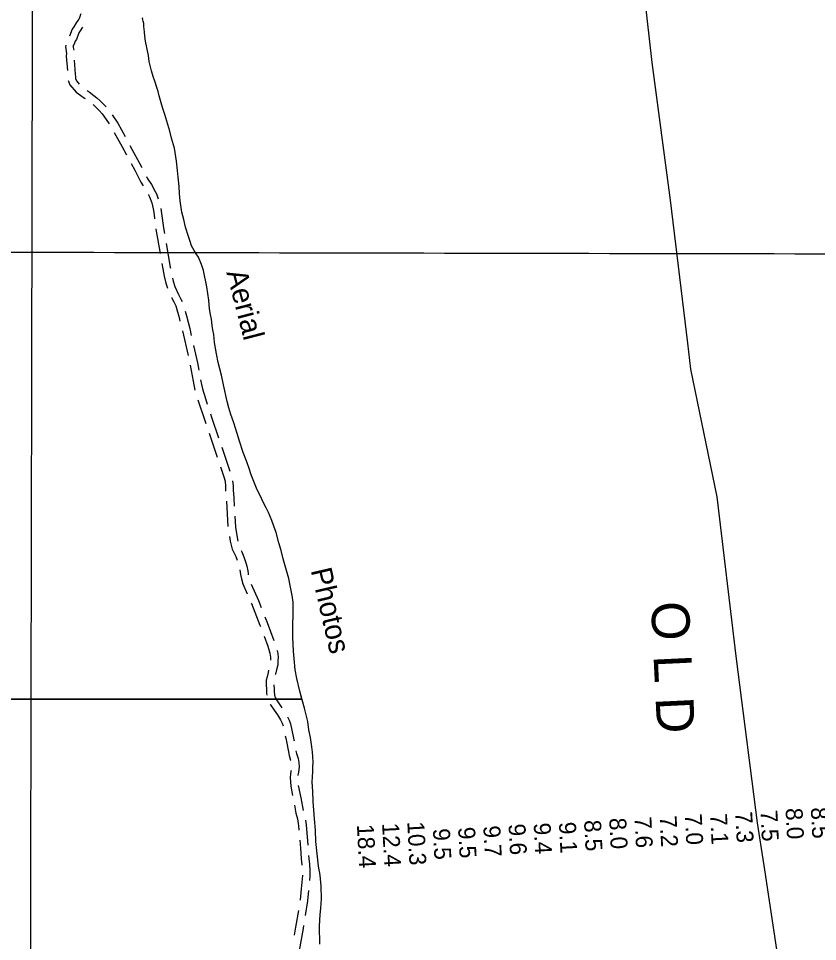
# Model space of a CAD drawing. Extents: x 3192952 to 3230831, y 849296 to 874698.
# Drawn here: x 3207564 to 3210731, y 858041 to 861699 of the extents above; entities that cross this region are included whole.
import ezdxf

# ---------------------------------------------------------------- set-up
doc = ezdxf.new("R2010")
doc.units = 0
for name, color, linetype in [('V-GRID-MAJR', 7, 'Continuous'), ('V-RIVR-IDEN', 7, 'Continuous'), ('V-RIVR-RANG', 7, 'Continuous'), ('V-ROAD-CNTR', 7, 'Continuous'), ('V-SITE-VEGE', 7, 'Continuous'), ('V-TOPO-BNDY', 7, 'Continuous'), ('V-TOPO-SHOR', 7, 'Continuous')]:
    doc.layers.add(name, color=color, linetype=linetype)

msp = doc.modelspace()

# ---------------------------------------------------------------- linework, layer by layer
at = {"layer": 'V-GRID-MAJR'}
for points in [[(3207605.446, 854713.525), (3207617.785, 860772.968), (3207630.13, 866835.496), (3207642.475, 872898.066), (3207642.481, 872901.108)], [(3197158.4390000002, 860795.787), (3202388.111, 860783.997), (3207617.785, 860772.968), (3212847.46, 860762.699), (3218077.137, 860753.191), (3223306.816, 860744.443), (3228536.495, 860736.457), (3228536.4960000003, 860736.457)]]:
    msp.add_spline(points, degree=3, dxfattribs=at)
at = {"layer": 'V-ROAD-CNTR'}
for p, q in [((3208213.826266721, 860461.4124769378), (3208235.912454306, 860363.8820339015)), ((3208319.3131240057, 860055.5952207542), (3208351.3451423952, 859960.8702590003)), ((3208369.8423514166, 859999.8213750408), (3208401.8743793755, 859905.0963849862))]:
    msp.add_line(p, q, dxfattribs=at)
for points in [[(3207810.4910056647, 861717.7183139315), (3207810.166320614, 861714.6589927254), (3207805.9629627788, 861701.3251246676), (3207802.9279060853, 861696.2592289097), (3207798.7438753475, 861691.4055059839), (3207793.0401801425, 861681.3239112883), (3207783.744000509, 861666.4862923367), (3207776.6917882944, 861656.738081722), (3207766.3573222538, 861629.6777769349), (3207766.0711100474, 861629.2217272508)], [(3207817.8928515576, 861664.4865559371), (3207808.635999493, 861649.7117076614), (3207803.3102117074, 861642.3499182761), (3207793.3326777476, 861616.2242230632), (3207788.6515859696, 861608.7653852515), (3207784.023901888, 861597.3117227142), (3207781.117668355, 861591.9579846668), (3207780.799636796, 861586.8994313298), (3207781.0024326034, 861583.5634402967), (3207782.9053705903, 861573.8982014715)], [(3207751.108880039, 861592.760320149), (3207750.7423632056, 861586.9305686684), (3207751.179567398, 861579.7385597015), (3207753.464551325, 861568.1328660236), (3207754.24587235, 861561.1190012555), (3207753.488454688, 861549.4553564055), (3207757.827223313, 861493.2453327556)], [(3207784.765945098, 861534.0612007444), (3207789.032446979, 861478.7874140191), (3207789.3764270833, 861468.0794587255), (3207790.248401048, 861461.0111736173), (3207793.7544302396, 861451.5380527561), (3207804.7092748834, 861439.035952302)], [(3207761.069248, 861453.4198467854), (3207767.541569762, 861435.931947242), (3207793.0741762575, 861406.7931304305), (3207811.558488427, 861394.3053975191), (3207826.1483414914, 861383.7408364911), (3207827.96742014, 861382.3509295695)], [(3207835.5430226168, 861413.9771914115), (3207844.0556585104, 861407.813163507), (3207862.185121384, 861393.960949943), (3207874.131601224, 861384.6147327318), (3207887.377152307, 861372.8806384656), (3207904.80635216, 861355.4194792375), (3207911.0167117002, 861348.7143631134)], [(3207859.378782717, 861357.6051754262), (3207866.7948476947, 861351.0353615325), (3207883.1776478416, 861334.6225207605), (3207895.4800179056, 861321.3400659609), (3207901.8996758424, 861312.6193779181), (3207922.9373808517, 861281.0113290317)], [(3207935.0993709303, 861316.8829561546), (3207957.241771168, 861283.6151605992), (3207986.4288158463, 861231.1525162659)], [(3207943.4460857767, 861246.7051299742), (3207974.641337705, 861190.6328066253), (3207991.71997077, 861159.1327808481)], [(3208005.7781263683, 861196.1455417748), (3208051.548795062, 861111.7255979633), (3208053.3290326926, 861108.1783880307)], [(3208010.7852074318, 861123.968640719), (3208024.949204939, 861097.8444020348), (3208048.550500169, 861050.8176751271), (3208058.6714469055, 861036.3613421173)], [(3208071.264056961, 861072.4419811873), (3208074.3814998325, 861066.230324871), (3208091.697612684, 861041.4967203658), (3208106.067436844, 861013.9675988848), (3208111.0300001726, 861004.0887278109), (3208118.0536102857, 860984.582159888)], [(3208078.591381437, 861001.7736310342), (3208079.364563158, 861000.2924011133), (3208083.413999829, 860992.2312721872), (3208091.8089061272, 860968.9162237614), (3208095.7293886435, 860956.5841595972), (3208097.8976867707, 860944.5548107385), (3208101.381360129, 860922.1315501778), (3208103.461084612, 860905.590613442)], [(3208128.039123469, 860945.9609314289), (3208131.092639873, 860926.3064498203), (3208138.269666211, 860869.2244951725), (3208142.1160402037, 860846.9765264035)], [(3208108.4510756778, 860865.9030840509), (3208108.590333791, 860864.7955048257), (3208125.435834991, 860767.3587539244)], [(3208148.9303067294, 860807.5618493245), (3208165.266307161, 860713.0721226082), (3208166.109371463, 860709.0525175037)], [(3208132.250103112, 860727.9440676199), (3208135.7956928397, 860707.43587739), (3208141.8498655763, 860678.5704829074), (3208148.5189270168, 860649.8889987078), (3208154.7134998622, 860630.6127085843)], [(3208174.648383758, 860669.9768699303), (3208177.4590729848, 860657.8890012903), (3208184.237335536, 860636.7963838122), (3208198.2098646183, 860605.8293442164), (3208205.959725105, 860589.2279226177), (3208212.155691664, 860577.6403510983)], [(3208170.654725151, 860593.9560699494), (3208170.9441353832, 860593.3146557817), (3208179.120274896, 860575.8000773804), (3208187.533714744, 860560.065432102), (3208192.128128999, 860546.0002088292), (3208200.236199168, 860513.7750938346), (3208203.7943121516, 860500.1330087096)], [(3208224.628762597, 860539.7777625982), (3208229.297800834, 860521.2209061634), (3208242.535841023, 860470.4652185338), (3208248.810774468, 860442.7557265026)], [(3208257.645249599, 860403.7435488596), (3208273.4048278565, 860334.150793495), (3208278.4223535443, 860305.9485617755)], [(3208244.5905502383, 860324.8382551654), (3208255.8478848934, 860261.5636492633), (3208263.4376528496, 860226.6590466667)], [(3208285.4595908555, 860266.5733548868), (3208293.1120922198, 860231.3802474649), (3208304.736866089, 860193.1602018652), (3208312.355726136, 860170.3804247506)], [(3208274.848595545, 860188.3314477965), (3208276.1551339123, 860184.0357981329), (3208301.0284636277, 860109.6665481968), (3208306.5003166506, 860093.4852054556)], [(3208325.0417167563, 860132.4503358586), (3208329.463536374, 860119.2294518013), (3208357.029540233, 860037.7113710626)], [(3208364.1579497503, 859922.9802742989), (3208377.578990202, 859883.2916250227), (3208382.7419333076, 859865.3729611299), (3208384.3722498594, 859845.783745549), (3208384.6227073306, 859828.9179394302), (3208384.8776013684, 859826.0001272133)], [(3208412.735401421, 859866.697669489), (3208414.3537501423, 859847.2522544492), (3208414.6032926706, 859830.4480605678), (3208417.1943600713, 859800.7877037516), (3208419.250378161, 859766.9456244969)], [(3208388.0296206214, 859786.128846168), (3208391.0832749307, 859735.8656643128), (3208393.621510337, 859686.2917666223)], [(3208421.5756497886, 859727.0166772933), (3208423.814214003, 859683.2956130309), (3208432.3706331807, 859633.859495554), (3208433.8675501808, 859627.9971998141)], [(3208399.686034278, 859646.7931595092), (3208403.0113668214, 859627.5805044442), (3208411.078163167, 859595.9889426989), (3208416.1719695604, 859585.6487192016), (3208422.074619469, 859572.6622872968), (3208424.8458515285, 859567.1299371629), (3208430.369970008, 859552.2027632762)], [(3208446.9666057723, 859590.3984400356), (3208449.151380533, 859585.5917127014), (3208452.408148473, 859579.0900628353), (3208458.6088668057, 859562.3345929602), (3208462.747547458, 859550.4803769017), (3208466.670168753, 859537.7251160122), (3208469.307587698, 859528.2734497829), (3208472.7337949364, 859509.6174113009), (3208473.9128072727, 859500.0755667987), (3208474.8223924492, 859494.8680180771)], [(3208441.458209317, 859513.8311753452), (3208443.068205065, 859505.0645886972), (3208444.2311927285, 859495.6524331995), (3208447.3240654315, 859477.9451467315), (3208453.155280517, 859458.1310611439), (3208470.3520918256, 859418.7485692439)], [(3208486.482476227, 859456.7757659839), (3208514.676913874, 859392.2075624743), (3208525.579288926, 859364.748229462)], [(3208486.359036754, 859382.0909954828), (3208486.9810861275, 859380.6664375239), (3208521.0385729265, 859294.8873419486), (3208523.211428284, 859289.1310641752)], [(3208540.3399105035, 859327.5713004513), (3208549.015427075, 859305.7206580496), (3208576.028159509, 859234.1591568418)], [(3208537.337559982, 859251.708445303), (3208552.363176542, 859211.9029320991), (3208560.4998666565, 859183.772744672), (3208562.856694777, 859167.645144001), (3208562.5272593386, 859155.7839975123)], [(3208588.169768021, 859196.0799926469), (3208589.888133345, 859190.139255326), (3208592.9173052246, 859169.4108559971), (3208592.4236639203, 859151.6375652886), (3208591.3484299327, 859137.0629202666), (3208586.7101800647, 859118.2422674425), (3208582.0750864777, 859100.3412163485), (3208581.499707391, 859097.8109476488)], [(3208555.2953049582, 859116.5988471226), (3208552.9209135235, 859107.4287836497), (3208549.0504586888, 859090.408195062), (3208546.245886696, 859076.6280064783), (3208545.5476452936, 859059.6231774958), (3208546.6880799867, 859039.3989886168), (3208547.172604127, 859025.832312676), (3208548.6437285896, 859017.8075316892)], [(3208575.66416573, 859058.4020059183), (3208576.6579200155, 859040.7790113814), (3208577.075395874, 859029.0896873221), (3208580.4547666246, 859010.6556860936), (3208580.6725353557, 859009.9436329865), (3208588.5765059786, 858994.518085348), (3208602.1506390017, 858975.5062032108), (3208607.979772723, 858966.8048938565)], [(3208562.0452771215, 858980.5098923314), (3208562.881494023, 858978.8779146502), (3208577.4753609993, 858958.4377967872), (3208590.0311802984, 858939.6953775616), (3208602.5407313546, 858919.195504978)], [(3208602.1585971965, 858919.8592600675), (3208609.1851699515, 858906.900016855), (3208612.7847332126, 858896.3278145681), (3208612.8998416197, 858895.7734752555)], [(3208629.5710516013, 858932.2412956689), (3208636.7668300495, 858918.9699831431), (3208641.781266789, 858904.24218543), (3208652.2884599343, 858853.6416222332), (3208655.5951069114, 858840.8048876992), (3208656.372503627, 858836.4893619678)], [(3208621.0282981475, 858856.6284369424), (3208623.0595400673, 858846.846377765), (3208626.26689309, 858834.395112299), (3208633.7203054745, 858793.0193355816), (3208637.332928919, 858778.5646214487), (3208642.6877530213, 858760.0765918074), (3208642.857137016, 858759.1340850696)], [(3208663.6096327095, 858797.1542785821), (3208666.303071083, 858786.3773785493), (3208671.93824698, 858766.9214081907), (3208674.9327049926, 858750.2592857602), (3208676.227052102, 858731.7882315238), (3208673.6036971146, 858712.1723415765), (3208671.679204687, 858700.5474840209), (3208671.565212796, 858698.9345284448)], [(3208644.3149168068, 858719.4875727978), (3208643.930302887, 858716.6116584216), (3208641.8527953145, 858704.0625159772), (3208640.9701064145, 858691.5726979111), (3208642.8039803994, 858656.7598690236), (3208650.058015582, 858620.4875259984)], [(3208672.944845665, 858659.0259119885), (3208682.496422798, 858611.2651728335), (3208691.878766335, 858560.8521750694)], [(3208657.575469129, 858581.2066744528), (3208663.5080967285, 858549.3296129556), (3208669.6346165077, 858527.9095946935), (3208674.1448423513, 858499.6289247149), (3208675.6718063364, 858483.0495303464)], [(3208700.961981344, 858521.9637523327), (3208703.9271576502, 858503.3710752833), (3208711.369446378, 858422.5645591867)], [(3208679.3391716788, 858443.2301915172), (3208682.3041854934, 858411.0368105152), (3208683.55447775, 858391.1289880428), (3208684.3050776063, 858368.3265972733), (3208686.8242215, 858345.4542258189), (3208686.9463266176, 858343.5700897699)], [(3208713.8497494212, 858382.6525925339), (3208714.2509223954, 858370.4654027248), (3208716.7177785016, 858348.0677741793), (3208718.3552840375, 858322.8003384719), (3208719.1615592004, 858301.9041965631), (3208717.2228703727, 858282.9621396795)], [(3208689.072644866, 858303.6300213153), (3208689.102440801, 858302.8578034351), (3208686.393163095, 858276.3866690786), (3208684.3000296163, 858249.3939477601), (3208679.8901619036, 858206.2089826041), (3208679.5468468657, 858204.1022899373)], [(3208713.8143758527, 858243.1102714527), (3208709.643838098, 858202.269017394), (3208700.162822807, 858144.0904257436)], [(3208673.113191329, 858164.6232882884), (3208662.312791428, 858098.3485238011), (3208656.4522183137, 858066.0248984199)], [(3208693.729166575, 858104.6114198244), (3208691.8792085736, 858093.2594761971), (3208676.0910593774, 858006.1809243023)]]:
    msp.add_lwpolyline(points, dxfattribs=at)
at = {"layer": 'V-SITE-VEGE'}
for p, q in [((3208055.7970000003, 861699.0279999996), (3208057.1420000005, 861702.9869999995)), ((3208058.375, 861688.4419999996), (3208055.7970000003, 861699.0279999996)), ((3208060.9620000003, 861679.1769999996), (3208058.375, 861688.4419999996)), ((3208060.89, 861667.2839999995), (3208060.9620000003, 861679.1769999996)), ((3208063.4050000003, 861646.1259999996), (3208060.89, 861667.2839999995)), ((3208064.619, 861628.9419999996), (3208063.4050000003, 861646.1259999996)), ((3208067.143, 861609.1049999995), (3208064.619, 861628.9419999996)), ((3208078.6890000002, 861552.2129999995), (3208067.143, 861609.1049999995)), ((3208082.509, 861528.4029999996), (3208078.6890000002, 861552.2129999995)), ((3208091.532, 861491.3489999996), (3208082.509, 861528.4029999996)), ((3208098.004, 861468.8429999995), (3208091.532, 861491.3489999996)), ((3208104.498, 861450.3049999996), (3208098.004, 861468.8429999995)), ((3208112.272, 861425.1509999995), (3208104.498, 861450.3049999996)), ((3208117.4620000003, 861409.2649999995), (3208112.272, 861425.1509999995)), ((3208121.322, 861392.0599999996), (3208117.4620000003, 861409.2649999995)), ((3208129.08, 861364.2619999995), (3208121.322, 861392.0599999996)), ((3208135.552, 861341.7589999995), (3208129.08, 861364.2619999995)), ((3208143.343, 861319.2469999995), (3208135.552, 861341.7589999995)), ((3208156.315, 861279.5239999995), (3208143.343, 861319.2469999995)), ((3208164.083, 861253.0499999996), (3208156.315, 861279.5239999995)), ((3208170.522, 861225.2599999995), (3208164.083, 861253.0499999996)), ((3208182.173, 861185.5459999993), (3208170.522, 861225.2599999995)), ((3208189.787, 861133.9649999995), (3208182.173, 861185.5459999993)), ((3208193.5270000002, 861096.9409999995), (3208189.787, 861133.9649999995)), ((3208197.33, 861070.4889999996), (3208193.5270000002, 861096.9409999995)), ((3208201.0670000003, 861033.4669999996), (3208197.33, 861070.4889999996)), ((3208202.221, 861005.7109999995), (3208201.0670000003, 861033.4669999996)), ((3208204.686, 860976.6229999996), (3208202.221, 861005.7109999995)), ((3208211.021, 860931.6549999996), (3208204.686, 860976.6229999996)), ((3208218.77, 860902.5359999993), (3208211.021, 860931.6549999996)), ((3208226.514, 860872.0969999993), (3208218.77, 860902.5359999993)), ((3208238.181, 860835.0259999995), (3208226.514, 860872.0969999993)), ((3208244.669, 860815.1649999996), (3208238.181, 860835.0259999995)), ((3208249.849, 860797.9549999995), (3208244.669, 860815.1649999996)), ((3208260.308, 860779.3899999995), (3208249.849, 860797.9549999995)), ((3208268.156, 860766.1289999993), (3208260.308, 860779.3899999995)), ((3208277.325, 860752.8579999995), (3208268.156, 860766.1289999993)), ((3208289.039, 860723.7149999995), (3208277.325, 860752.8579999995)), ((3208296.826, 860699.8829999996), (3208289.039, 860723.7149999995)), ((3208310.965, 860635.0469999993), (3208296.826, 860699.8829999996)), ((3208314.768, 860608.5949999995), (3208310.965, 860635.0469999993)), ((3208318.58, 860583.4639999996), (3208314.768, 860608.5949999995)), ((3208321.0130000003, 860549.0929999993), (3208318.58, 860583.4639999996)), ((3208324.84, 860526.6059999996), (3208321.0130000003, 860549.0929999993)), ((3208328.693, 860508.0809999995), (3208324.84, 860526.6059999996)), ((3208331.181, 860482.9589999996), (3208328.693, 860508.0809999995)), ((3208333.721, 860465.7659999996), (3208331.181, 860482.9589999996)), ((3208337.573, 860447.2419999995), (3208333.721, 860465.7659999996)), ((3208341.343, 860415.5039999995), (3208337.573, 860447.2419999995)), ((3208348.999, 860370.5299999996), (3208341.343, 860415.5039999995)), ((3208355.397, 860336.1329999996), (3208348.999, 860370.5299999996)), ((3208368.305, 860285.8409999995), (3208355.397, 860336.1329999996)), ((3208375.999, 860247.4709999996), (3208368.305, 860285.8409999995)), ((3208391.454, 860181.3069999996), (3208375.999, 860247.4709999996)), ((3208397.907, 860156.1589999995), (3208391.454, 860181.3069999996)), ((3208405.6750000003, 860129.6849999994), (3208397.907, 860156.1589999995)), ((3208417.367, 860096.5769999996), (3208405.6750000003, 860129.6849999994)), ((3208430.323, 860054.2119999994), (3208417.367, 860096.5769999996)), ((3208439.387, 860023.7639999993), (3208430.323, 860054.2119999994)), ((3208454.97, 859978.7389999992), (3208439.387, 860023.7639999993)), ((3208469.282, 859941.6539999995), (3208454.97, 859978.7389999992)), ((3208478.369, 859915.1689999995), (3208469.282, 859941.6539999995)), ((3208486.145, 859890.0159999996), (3208478.369, 859915.1689999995)), ((3208509.576, 859831.7289999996), (3208486.145, 859890.0159999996)), ((3208521.332, 859809.1929999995), (3208509.5760000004, 859831.7289999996)), ((3208535.69, 859780.0359999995), (3208521.332, 859809.1929999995)), ((3208546.139, 859760.1499999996), (3208535.69, 859780.0359999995)), ((3208555.2770000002, 859741.5949999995), (3208546.139, 859760.1499999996)), ((3208568.298, 859709.7999999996), (3208555.2770000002, 859741.5949999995)), ((3208576.089, 859687.2879999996), (3208568.298, 859709.7999999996)), ((3208585.186, 859662.1259999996), (3208576.089, 859687.2879999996)), ((3208595.508, 859621.0989999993), (3208585.186, 859662.1259999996)), ((3208604.571, 859590.6509999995), (3208595.508, 859621.0989999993)), ((3208613.623, 859557.5599999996), (3208604.571, 859590.6509999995)), ((3208626.554, 859511.2319999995), (3208613.623, 859557.5599999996)), ((3208635.61, 859479.4609999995), (3208626.554, 859511.2319999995)), ((3208640.728, 859451.6799999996), (3208635.61, 859479.4609999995)), ((3208648.414, 859411.9919999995), (3208640.728, 859451.6799999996)), ((3208652.217, 859385.5399999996), (3208648.414, 859411.9919999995)), ((3208651.374, 859246.7959999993), (3208652.217, 859385.5399999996)), ((3208653.678, 859191.2809999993), (3208651.374, 859246.7959999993)), ((3208656.143, 859162.1949999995), (3208653.678, 859191.2809999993)), ((3208661.157, 859117.2329999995), (3208656.143, 859162.1949999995)), ((3208667.563, 859084.1579999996), (3208661.157, 859117.2329999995)), ((3208679.149, 859033.8739999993), (3208667.563, 859084.1579999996)), ((3208687.468, 859002.2099999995), (3208679.149, 859033.8739999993)), ((3207018.754, 859002.2099999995), (3208687.468, 859002.2099999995)), ((3208687.468, 859002.2099999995), (3207018.754, 859002.2099999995)), ((3208688.1900000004, 858999.4609999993), (3208687.468, 859002.2099999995)), ((3208697.2380000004, 858966.3719999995), (3208688.1900000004, 858999.4609999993)), ((3208710.131, 858913.4349999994), (3208697.238, 858966.3719999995)), ((3208715.216, 858880.3699999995), (3208710.131, 858913.4349999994)), ((3208721.636, 858849.9369999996), (3208715.216, 858880.3699999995)), ((3208726.697, 858812.9069999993), (3208721.636, 858849.9369999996)), ((3208729.2120000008, 858791.7489999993), (3208726.697, 858812.9069999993)), ((3208730.428, 858774.5619999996), (3208729.2120000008, 858791.7489999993)), ((3208731.606, 858750.7679999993), (3208730.428, 858774.5619999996)), ((3208730.066, 858715.0979999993), (3208730.179, 858733.5979999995)), ((3208730.1790000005, 858733.5979999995), (3208731.6060000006, 858750.7679999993)), ((3208728.487, 858672.8239999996), (3208730.066, 858715.0979999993)), ((3208730.914, 858637.1289999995), (3208728.487, 858672.8239999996)), ((3208731.985, 858596.1589999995), (3208730.914, 858637.1289999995)), ((3208736.853, 858527.4159999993), (3208731.985, 858596.1589999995)), ((3208740.543, 858482.4619999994), (3208736.853, 858527.4159999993)), ((3208742.913, 858437.5209999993), (3208740.543, 858482.4619999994)), ((3208752.889, 858339.6729999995), (3208742.913, 858437.5209999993)), ((3208759.279, 858303.9559999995), (3208752.889, 858339.6729999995)), ((3208762.977, 858260.3279999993), (3208759.279, 858303.9559999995)), ((3208765.3140000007, 858210.0979999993), (3208762.9770000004, 858260.3279999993)), ((3208762.447, 858173.1159999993), (3208765.3140000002, 858210.0979999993)), ((3208756.727, 858101.7919999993), (3208759.6510000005, 858148.0279999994)), ((3208759.6510000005, 858148.0279999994), (3208762.447, 858173.1159999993)), ((3208758.9340000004, 858030.4209999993), (3208756.7270000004, 858101.7919999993))]:
    msp.add_line(p, q, dxfattribs=at)
at = {"layer": 'V-TOPO-BNDY'}
for p, q in [((3209999.691000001, 862195.7669999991), (3210074.052000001, 861524.8069999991)), ((3210074.052000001, 861524.8069999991), (3210146.991000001, 860978.912999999)), ((3210146.991000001, 860978.912999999), (3210215.353000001, 860412.0809999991)), ((3210215.353000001, 860412.0809999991), (3210227.617000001, 860309.8289999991)), ((3210227.617000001, 860309.8289999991), (3210331.338000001, 859803.5179999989)), ((3210331.338000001, 859803.5179999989), (3210407.282000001, 859172.5769999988)), ((3210407.282000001, 859172.5769999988), (3210414.880000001, 859109.7769999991)), ((3210414.880000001, 859109.7769999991), (3210491.956000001, 858510.981999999)), ((3210491.956000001, 858510.981999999), (3210520.378000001, 858325.785999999)), ((3210520.378000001, 858325.785999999), (3210581.919000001, 857917.903999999))]:
    msp.add_line(p, q, dxfattribs=at)
at = {"layer": 'V-TOPO-SHOR'}
for points in [[(3208535.690000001, 859780.035999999), (3208521.332000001, 859809.192999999), (3208509.576000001, 859831.7289999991), (3208486.145000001, 859890.015999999), (3208478.369000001, 859915.1689999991), (3208469.282000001, 859941.653999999), (3208454.970000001, 859978.7409999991), (3208439.387000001, 860023.763999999), (3208430.323000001, 860054.211999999), (3208417.367000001, 860096.5769999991), (3208405.675000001, 860129.684999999), (3208397.907000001, 860156.158999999), (3208391.454000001, 860181.3069999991), (3208375.9990000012, 860247.4709999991), (3208368.3030000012, 860285.8409999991), (3208355.397000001, 860336.1329999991), (3208348.9990000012, 860370.5299999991), (3208341.343000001, 860415.503999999), (3208337.573000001, 860447.241999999), (3208333.721000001, 860465.765999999), (3208331.181000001, 860482.9589999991), (3208328.693000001, 860508.0809999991), (3208324.8400000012, 860526.6059999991), (3208321.013000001, 860549.0929999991), (3208318.580000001, 860583.4639999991), (3208314.768000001, 860608.594999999), (3208310.9650000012, 860635.0469999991), (3208296.824000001, 860699.8829999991), (3208289.039000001, 860723.714999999), (3208277.325000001, 860752.8579999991), (3208268.156000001, 860766.128999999), (3208260.308000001, 860779.3899999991), (3208249.849000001, 860797.954999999), (3208244.667000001, 860815.1649999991), (3208238.181000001, 860835.025999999), (3208226.514000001, 860872.096999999), (3208218.770000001, 860902.535999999), (3208211.021000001, 860931.6569999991), (3208204.686000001, 860976.6229999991), (3208202.221000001, 861005.7109999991), (3208201.067000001, 861033.466999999), (3208197.330000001, 861070.488999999), (3208193.527000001, 861096.9409999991), (3208189.787000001, 861133.964999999), (3208182.173000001, 861185.545999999), (3208170.522000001, 861225.2599999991), (3208164.083000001, 861253.0499999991), (3208156.315000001, 861279.523999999), (3208143.343000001, 861319.246999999), (3208135.552000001, 861341.758999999), (3208129.080000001, 861364.261999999), (3208121.322000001, 861392.059999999), (3208117.462000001, 861409.2629999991), (3208112.272000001, 861425.150999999), (3208104.498000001, 861450.3049999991), (3208098.004000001, 861468.844999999), (3208091.532000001, 861491.3489999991), (3208082.509000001, 861528.4029999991), (3208078.689000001, 861552.212999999), (3208067.143000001, 861609.104999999), (3208064.619000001, 861628.9419999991), (3208063.405000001, 861646.1259999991), (3208060.890000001, 861667.283999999), (3208060.962000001, 861679.1769999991), (3208058.375000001, 861688.4439999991), (3208055.797000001, 861699.0299999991), (3208057.142000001, 861702.986999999)], [(3208758.934000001, 858030.420999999), (3208756.727000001, 858101.7919999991), (3208759.651000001, 858148.025999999), (3208762.447000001, 858173.1159999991), (3208765.314000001, 858210.0979999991), (3208762.977000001, 858260.327999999), (3208759.279000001, 858303.9559999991), (3208752.889000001, 858339.672999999), (3208742.913000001, 858437.520999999), (3208740.543000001, 858482.4639999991), (3208736.853000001, 858527.415999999), (3208731.985000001, 858596.158999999), (3208730.914000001, 858637.128999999), (3208728.487000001, 858672.8239999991), (3208730.066000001, 858715.0979999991), (3208730.179000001, 858733.5979999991), (3208731.606000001, 858750.7679999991), (3208730.4280000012, 858774.5619999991), (3208729.212000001, 858791.748999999), (3208726.697000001, 858812.9069999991), (3208721.636000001, 858849.9369999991), (3208715.216000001, 858880.3699999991), (3208710.131000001, 858913.434999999), (3208697.238000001, 858966.371999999), (3208688.190000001, 858999.4609999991), (3208679.149000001, 859033.873999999), (3208667.563000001, 859084.157999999), (3208661.157000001, 859117.2329999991), (3208656.143000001, 859162.192999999), (3208653.6780000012, 859191.280999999), (3208651.3740000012, 859246.7939999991), (3208652.217000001, 859385.5399999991), (3208648.414000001, 859411.991999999), (3208640.728000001, 859451.6799999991), (3208635.610000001, 859479.4609999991), (3208626.554000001, 859511.231999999), (3208613.623000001, 859557.559999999), (3208604.573000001, 859590.650999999), (3208595.508000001, 859621.0989999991), (3208585.186000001, 859662.1259999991), (3208576.089000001, 859687.287999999), (3208568.298000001, 859709.7999999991), (3208555.277000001, 859741.594999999), (3208546.139000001, 859760.1499999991), (3208535.690000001, 859780.035999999)]]:
    msp.add_lwpolyline(points, dxfattribs=at)

# ---------------------------------------------------------------- texts
at = {"layer": 'V-RIVR-IDEN'}
for s, height, rotation, p in [('Aerial', 82.99999799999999, 284.57458435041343, (3208387.278, 860692.968)), ('Photos', 82.99999799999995, 283.05032404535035, (3208721.838, 859512.782)), ('O L D', 149.99999999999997, 272.739376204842, (3210070.678561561, 859386.0466710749))]:
    msp.add_text(s, height=height, rotation=rotation, dxfattribs=at).set_placement(p)
at = {"layer": 'V-RIVR-RANG'}
for s, p in [('7.0', (3210204.72424673, 858546.6876364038)), ('7.1', (3210304.848793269, 858546.9925106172)), ('7.3', (3210404.5675473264, 858554.9361672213)), ('7.5', (3210504.4125473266, 858560.5091672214)), ('8.0', (3210604.10224673, 858568.9796364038)), ('8.5', (3210704.1015473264, 858571.6551672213)), ('10.3', (3209104.820104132, 858515.6763596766)), ('9.4', (3209605.8105473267, 858510.3521672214)), ('9.1', (3209705.7817932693, 858513.5545106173)), ('8.5', (3209805.4995473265, 858521.4981672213)), ('8.0', (3209905.19024673, 858529.9686364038)), ('7.6', (3210005.091356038, 858534.4880112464)), ('7.2', (3210105.0335473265, 858538.2171672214)), ('18.4', (3208905.1311041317, 858504.5303596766)), ('12.4', (3209004.976104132, 858510.1033596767)), ('9.5', (3209206.4325473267, 858488.0601672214)), ('9.5', (3209306.2775473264, 858493.6331672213)), ('9.7', (3209406.1215473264, 858499.2061672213)), ('9.6', (3209505.8683560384, 858506.6230112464))]:
    msp.add_text(s, height=66.99999999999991, rotation=273.04832571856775, dxfattribs=at).set_placement(p)

doc.saveas('drawing.dxf')
